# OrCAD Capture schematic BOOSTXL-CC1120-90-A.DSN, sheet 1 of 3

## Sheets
1 CC2511: size B; title: BOOSTXL-CC1120-90; rev: A
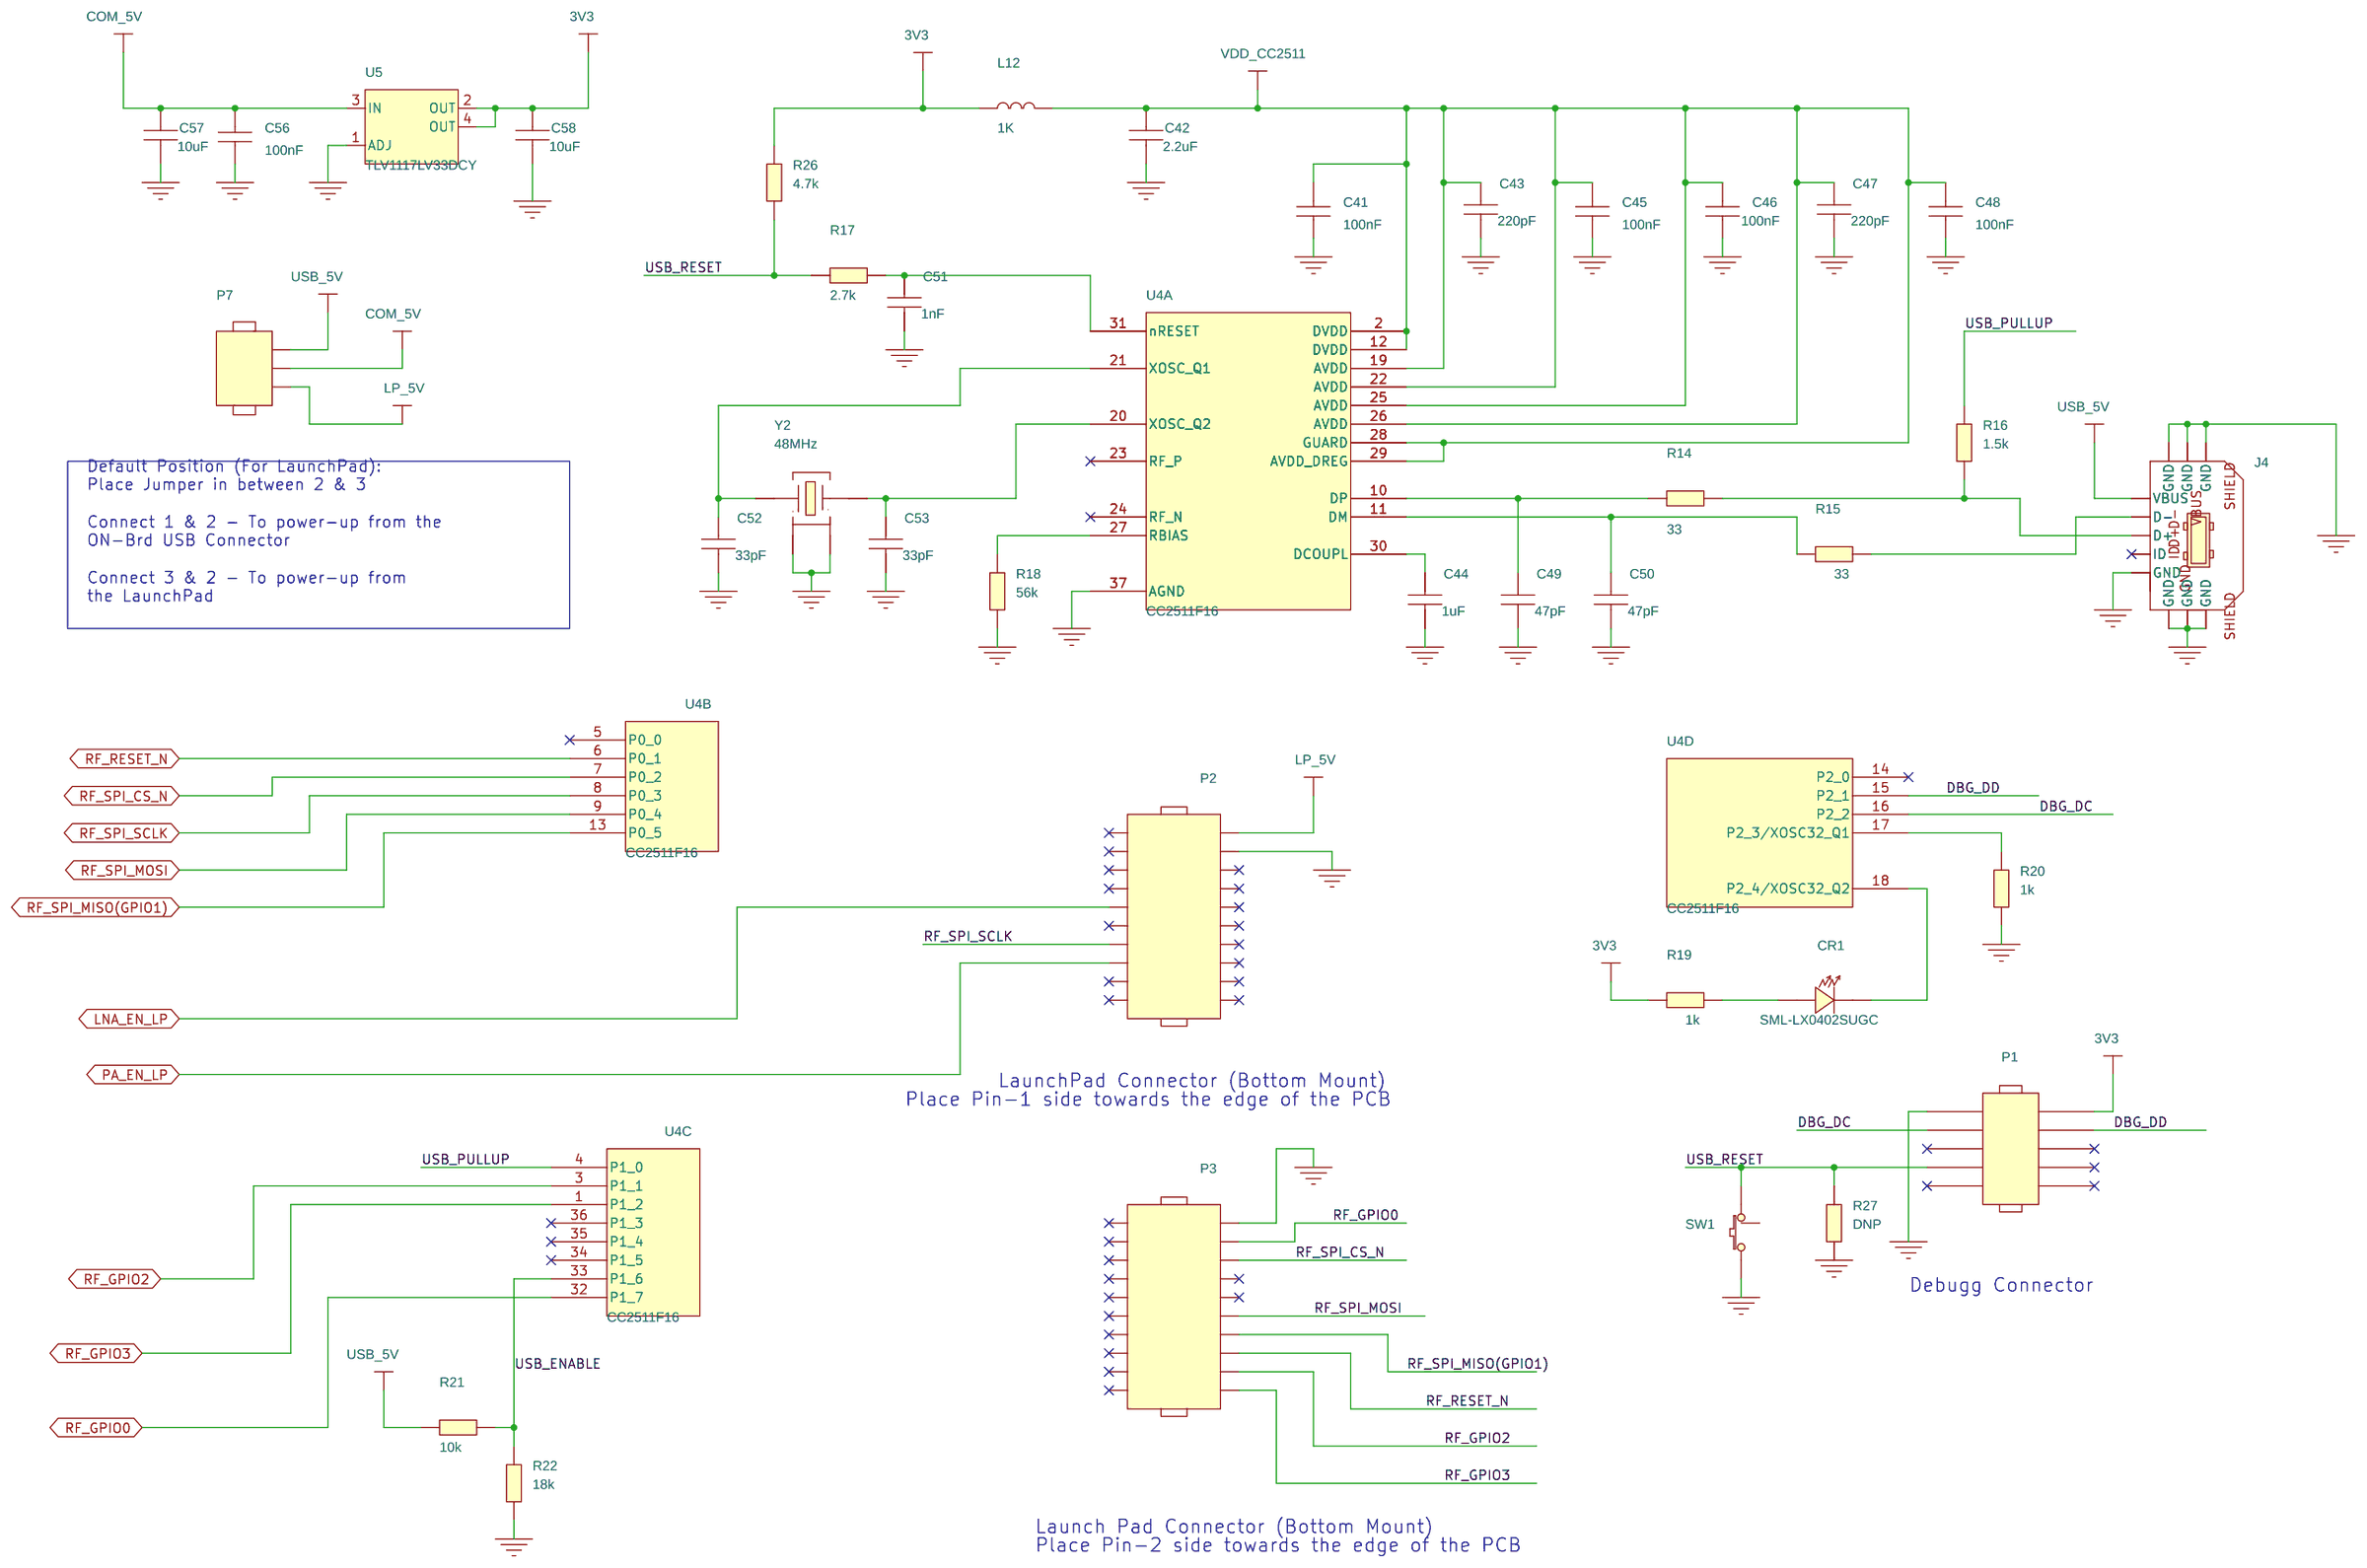
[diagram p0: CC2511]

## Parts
C41  100nF  [CAPC1005X60N]
C42  2.2uF  [CAPC1608X90N]
C43  220pF  [CAPC1005X60N]
C44  1uF  [CAPC1005X60N]
C45  100nF  [CAPC1005X60N]
C46  100nF  [CAPC1005X60N]
C47  220pF  [CAPC1005X60N]
C48  100nF  [CAPC1005X60N]
C49  47pF  [CAPC1005X60N]
C50  47pF  [CAPC1005X60N]
C51  1nF  [CAPC1005X60N]
C52  33pF  [CAPC1005X60N]
C53  33pF  [CAPC1005X60N]
C56  100nF  [CAPC1005X60N]
C57  10uF  [CAPC1608X100N]
C58  10uF  [CAPC1608X100N]
CR1  SML-LX0402SUGC  [LEDC1005X70N]
J4  1981568-1  [TYCO_19815681N]
L12  1K  [INDC1005X60N]
P1  FTSH-105-01-L-DV-K  [SAMTEC_FTSH-105-01-L-DV-K-10CN]
P2  SSW-110-23-F-D  [SAMTEC_TSW11008SDB]
P3  SSW-110-23-F-D  [SAMTEC_TSW11008SDB]
P7  TSM-103-01-L-SV-P  [SAMTEC_TSM10301LSVPN]
R14  33  [RESC1005X40N]
R15  33  [RESC1005X40N]
R16  1.5k  [RESC1005X40N]
R17  2.7k  [RESC1005X40N]
R18  56k  [RESC1005X40N]
R19  1k  [RESC1005X40N]
R20  1k  [RESC1005X40N]
R21  10k  [RESC1005X40N]
R22  18k  [RESC1005X40N]
R26  4.7k  [RESC1005X40N]
R27  DNP  [RESC1005X40N]
SW1  B3U-1000PM  [SW_B3U-1000PN]
U4  CC2511F16  [QFNWB50P600X600X90-37N]  (sections A,B,C,D)
U5  TLV1117LV33DCY  [SOT230P700X180-4AN]
Y2  48MHz  [XTAL_FA128N]

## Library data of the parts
C41 C45 C46 C48 C56 = CAPACITOR: CAPACITOR, CERAMIC X7R, 100nF, 10V, -10%/+10%, -55DEGC/+125DEGC, 0402, SMD; ALT_SYMBOLS: CAPC1005X60L,CAPC1005X60M; AutoDoc File: http://notefied-dynamic-precision.com/DB/Apps/Desktop/Item/Object.aspx?id=49911; Budget Currency: EUR; Budget Price: 0.006; Datasheet URL 1: http://search.murata.co.jp/Ceramy/image/img/w_hinm/L0005E.pdf; Datasheet URL 2: http://psearch.murata.com/capacitor/product/GRM155R71A104KA01%23.pdf; Definied Quality: INDUSTRIAL; Dielectric Type: X7R; Esd Level: N/A; FPLIST: CAPC1005X60N,CAPC1005X60L,CAPC1005X60M; Last Time Buy: N/A; Lead Time: 14; LifeCycle Status: GROWTH; MPN: GRM155R71A104KA01D; MPN Status: NRND; MSL: 1; MTBF: N/A; MTBF Standard: N/A; Manufacturer: MURATA; Max Oper Temp: +125DEGC; Max Tol: +10%; Min Oper Temp: -55DEGC; Min Tol: -10%; Mounting Type: SMD; NOTE Status: PREFERRED; Old Footprint: CAPC1005X60N,0402; PCB Package: 0402; Packing Size: 10000; Packing Type: TAPE_&_REEL; Part Number: 02-00760; Part Type: CAPACITOR\CERAMIC\0402; Revision: R008; RoHS Status: ROHS_COMPLIANT; Rtd Voltage: 10V; WEIGHT: 0.0016g
C42 = CAPACITOR: CAPACITOR, CERAMIC X5R, 2.2uF, 10V, -20%/+20%, -55DEGC/+85DEGC, 0603, SMD; ALT_SYMBOLS: CAPC1608X90L,CAPC1608X90M; AutoDoc File: http://notefied-dynamic-precision.com/DB/Apps/Desktop/Item/Object.aspx?id=50283; Budget Currency: EUR; Budget Price: 0.03; Datasheet URL 1: http://search.murata.co.jp/Ceramy/image/img/w_hinm/L0005E.pdf; Datasheet URL 2: http://psearch.murata.com/capacitor/product/GRM188R61A225ME34%23.pdf; Definied Quality: INDUSTRIAL; Dielectric Type: X5R; Esd Level: N/A; FPLIST: CAPC1608X90N,CAPC1608X90L,CAPC1608X90M; Last Time Buy: N/A; Lead Time: 10; LifeCycle Status: GROWTH; MPN: GRM188R61A225ME34D; MPN Status: NRND; MSL: 1; MTBF: N/A; MTBF Standard: N/A; Manufacturer: MURATA; Max Oper Temp: +85DEGC; Max Tol: +20%; Min Oper Temp: -55DEGC; Min Tol: -20%; Mounting Type: SMD; NOTE Status: PREFERRED; Old Footprint: CAPC1608X90N,0603; PCB Package: 0603; Packing Size: 4000; Packing Type: TAPE_&_REEL; Part Number: 02-01132; Part Type: CAPACITOR\CERAMIC\0603; Revision: R002; RoHS Status: ROHS_COMPLIANT; Rtd Voltage: 10V; WEIGHT: 0.0063g
C43 C47 = CAPACITOR: CAPACITOR, CERAMIC C0G/NP0, 220pF, 50V, -5%/+5%, -55DEGC/+125DEGC, 0402, SMD; ALT_SYMBOLS: CAPC1005X60L,CAPC1005X60M; AutoDoc File: http://notefied-dynamic-precision.com/DB/Apps/Desktop/Item/Object.aspx?id=50427; Budget Currency: EUR; Budget Price: 0.006; Datasheet URL 1: http://search.murata.co.jp/Ceramy/image/img/w_hinm/L0005E.pdf; Datasheet URL 2: http://psearch.murata.com/capacitor/product/GRM1555C1H221JA01%23.pdf; Definied Quality: INDUSTRIAL; Dielectric Type: C0G/NP0; Esd Level: N/A; FPLIST: CAPC1005X60N,CAPC1005X60L,CAPC1005X60M; Last Time Buy: N/A; Lead Time: 12; LifeCycle Status: GROWTH; MPN: GRM1555C1H221JA01D; MPN Status: ACTIVE; MSL: 1; MTBF: N/A; MTBF Standard: N/A; Manufacturer: MURATA; Max Oper Temp: +125DEGC; Max Tol: +5%; Min Oper Temp: -55DEGC; Min Tol: -5%; Mounting Type: SMD; NOTE Status: PREFERRED; Old Footprint: CAPC1005X60N,0402; PCB Package: 0402; Packing Size: 10000; Packing Type: TAPE_&_REEL; Part Number: 02-01276; Part Type: CAPACITOR\CERAMIC\0402; Revision: R001; RoHS Status: ROHS_COMPLIANT; Rtd Voltage: 50V; WEIGHT: 0.0016g
C44 = CAPACITOR: CAPACITOR, CERAMIC X5R, 1uF, 10V, -10%/+10%, -55DEGC/+85DEGC, 0402, SMD; ALT_SYMBOLS: CAPC1005X60L,CAPC1005X60M; AutoDoc File: http://notefied-dynamic-precision.com/DB/Apps/Desktop/Item/Object.aspx?id=74236; Budget Currency: EUR; Budget Price: 0.015; Datasheet URL 1: http://search.murata.co.jp/Ceramy/image/img/w_hinm/L0005E.pdf; Datasheet URL 2: http://psearch.murata.com/capacitor/product/GRM155R61A105KE15%23.pdf; Definied Quality: INDUSTRIAL; Dielectric Type: X5R; Esd Level: N/A; FPLIST: CAPC1005X60N,CAPC1005X60L,CAPC1005X60M; Last Time Buy: N/A; Lead Time: 14; MPN: GRM155R61A105KE15D; MPN Status: NRND; MSL: 1; MTBF: N/A; MTBF Standard: N/A; Manufacturer: MURATA; Max Oper Temp: +85DEGC; Max Tol: +10%; Min Oper Temp: -55DEGC; Min Tol: -10%; Mounting Type: SMD; NOTE Status: PREFERRED; Old Footprint: CAPC1005X60N,0402; PCB Package: 0402; Packing Size: 10000; Packing Type: TAPE_&_REEL; Part Number: 02-02381; Part Type: CAPACITOR\CERAMIC\0402; Revision: R005; RoHS Status: ROHS_COMPLIANT; Rtd Voltage: 10V; WEIGHT: 0.0016g
C49 C50 = CAPACITOR: CAPACITOR, CERAMIC C0G/NP0, 47pF, 50V, -5%/+5%, -55DEGC/+125DEGC, 0402, SMD; ALT_SYMBOLS: CAPC1005X60L,CAPC1005X60M; AutoDoc File: http://notefied-dynamic-precision.com/DB/Apps/Desktop/Item/Object.aspx?id=86073; Budget Currency: EUR; Budget Price: 0.006; Datasheet URL 1: http://search.murata.co.jp/Ceramy/image/img/w_hinm/L0005E.pdf; Datasheet URL 2: http://psearch.murata.com/capacitor/product/GRM1555C1H470JA01%23.pdf; Definied Quality: INDUSTRIAL; Dielectric Type: C0G/NP0; Esd Level: N/A; FPLIST: CAPC1005X60N,CAPC1005X60L,CAPC1005X60M; Last Time Buy: N/A; Lead Time: 12; MPN: GRM1555C1H470JA01D; MPN Status: ACTIVE; MSL: 1; MTBF: N/A; MTBF Standard: N/A; Manufacturer: MURATA; Max Oper Temp: +125DEGC; Max TC: +30PPM/DEGC; Max Tol: +5%; Min Oper Temp: -55DEGC; Min TC: -30PPM/DEGC; Min Tol: -5%; Mounting Type: SMD; NOTE Status: PREFERRED; PCB Package: 0402; Packing Size: 10000; Packing Type: TAPE_&_REEL; Part Number: 02-04366; Part Type: CAPACITOR\CERAMIC\0402; Revision: R001; RoHS Status: ROHS_COMPLIANT; Rtd Voltage: 50V; WEIGHT: 0.0016g
C51 = CAPACITOR: CAPACITOR, CERAMIC X7R, 1nF, 50V, -10%/+10%, -55DEGC/+125DEGC, 0402, SMD; ALT_SYMBOLS: CAPC1005X60L,CAPC1005X60M; AutoDoc File: http://notefied-dynamic-precision.com/DB/Apps/Desktop/Item/Object.aspx?id=72148; Budget Currency: EUR; Budget Price: 0.003; Datasheet URL 1: http://search.murata.co.jp/Ceramy/image/img/w_hinm/L0005E.pdf; Datasheet URL 2: http://psearch.murata.com/capacitor/product/GRM155R71H102KA01%23.pdf; Definied Quality: INDUSTRIAL; Dielectric Type: X7R; Esd Level: N/A; FPLIST: CAPC1005X60N,CAPC1005X60L,CAPC1005X60M; Last Time Buy: N/A; Lead Time: 10; LifeCycle Status: GROWTH; MPN: GRM155R71H102KA01D; MPN Status: ACTIVE; MSL: 1; MTBF: N/A; MTBF Standard: N/A; Manufacturer: MURATA; Max Oper Temp: +125DEGC; Max Tol: +10%; Min Oper Temp: -55DEGC; Min Tol: -10%; Mounting Type: SMD; NOTE Status: PREFERRED; Old Footprint: CAPC1005X60N,0402; PCB Package: 0402; Packing Size: 10000; Packing Type: TAPE_&_REEL; Part Number: 02-02070; Part Type: CAPACITOR\CERAMIC\0402; Revision: R000; RoHS Status: ROHS_COMPLIANT; Rtd Voltage: 50V; WEIGHT: 0.0016g
C52 C53 = CAPACITOR: CAPACITOR, CERAMIC C0G/NP0, 33pF, 50V, -5%/+5%, -55DEGC/+125DEGC, 0402, SMD; ALT_SYMBOLS: CAPC1005X60M,CAPC1005X60L; AutoDoc File: http://notefied-dynamic-precision.com/DB/Apps/Desktop/Item/Object.aspx?id=86036; Budget Currency: EUR; Budget Price: 0.006; Datasheet URL 1: http://search.murata.co.jp/Ceramy/image/img/w_hinm/L0005E.pdf; Datasheet URL 2: http://psearch.murata.com/capacitor/product/GRM1555C1H330JA01%23.pdf; Definied Quality: INDUSTRIAL; Dielectric Type: C0G/NP0; Esd Level: N/A; FPLIST: CAPC1005X60N,CAPC1005X60M,CAPC1005X60L; Last Time Buy: N/A; Lead Time: 12; MPN: GRM1555C1H330JA01D; MPN Status: ACTIVE; MSL: 1; MTBF: N/A; MTBF Standard: N/A; Manufacturer: MURATA; Max Oper Temp: +125DEGC; Max TC: +30PPM/DEGC; Max Tol: +5%; Min Oper Temp: -55DEGC; Min TC: -30PPM/DEGC; Min Tol: -5%; Mounting Type: SMD; NOTE Status: PREFERRED; PCB Package: 0402; Packing Size: 10000; Packing Type: TAPE_&_REEL; Part Number: 02-04354; Part Type: CAPACITOR\CERAMIC\0402; Revision: R003; RoHS Status: ROHS_COMPLIANT; Rtd Voltage: 50V; WEIGHT: 0.0016g
C57 C58 = CAPACITOR: CAPACITOR, CERAMIC X5R, 10uF, 16V, -20%/+20%, -55DEGC/+85DEGC, 0603, SMD; ALT_SYMBOLS: CAPC1608X100L,CAPC1608X100M; AutoDoc File: http://notefied-dynamic-precision.com/DB/Apps/Desktop/Item/Object.aspx?id=94995; Budget Currency: EUR; Budget Price: 0.12; Datasheet URL 1: N/A; Datasheet URL 2: http://www.yuden.co.jp/eu/product/category/capacitor/EMK107BBJ106MA-T.pdf; Definied Quality: INDUSTRIAL; Dielectric Type: X5R; Esd Level: N/A; FPLIST: CAPC1608X100N,CAPC1608X100L,CAPC1608X100M; Last Time Buy: N/A; Lead Time: 5; MPN: EMK107BBJ106MA-T; MPN Status: ACTIVE; MSL: N/A; MTBF: N/A; MTBF Standard: N/A; Manufacturer: TAIYO YUDEN; Max Oper Temp: +85DEGC; Max Tol: +20%; Min Oper Temp: -55DEGC; Min Tol: -20%; Mounting Type: SMD; NOTE Status: PREFERRED; PCB Package: 0603; Packing Size: 4000; Packing Type: TAPE_&_REEL; Part Number: 02-05939; Part Type: CAPACITOR\CERAMIC\0603; Revision: R001; RoHS Status: ROHS_COMPLIANT; Rtd Voltage: 16V; WEIGHT: N/A
CR1 = LED_AC_0: OPTO, LED, GREEN COLOR, 574nm, 0.025A, 0.1W, 0402, SMD; ALT_SYMBOLS: LEDC1005X70L,LEDC1005X70M; AutoDoc File: http://notefied-dynamic-precision.com/DB/Apps/Desktop/Item/Object.aspx?id=80253; Budget Currency: EUR; Budget Price: 0.325; Datasheet URL 1: http://www.lumex.com/images/Lumex_RoHS_Declaration_2008.doc.pdf; Datasheet URL 2: http://www.lumex.com/specs/SML-LX0402SUGC-TR.pdf; Definied Quality: INDUSTRIAL; Esd Level: N/A; FPLIST: LEDC1005X70N,LEDC1005X70L,LEDC1005X70M; Last Time Buy: N/A; Lead Time: 12; MPN: SML-LX0402SUGC-TR; MPN Status: ACTIVE; MSL: 3; MTBF: 3.55*10^7; MTBF Standard: CL=60%,Ta=100degC,Ea=0.7eV,Ts=40degC; Manufacturer: LUMEX; Max Oper Temp: +85DEGC; Min Oper Temp: -40DEGC; Mounting Type: SMD; NOTE Status: PREFERRED; PCB Package: 0402; Packing Size: 2000; Packing Type: TAPE_&_REEL; Part Number: 15-00978; Part Type: OPTO\LED\0402; Revision: R001; RoHS Status: ROHS_COMPLIANT; Rtd Current: 0.025A; Rtd Power: 0.1W; Rtd Voltage: 2.2V; WEIGHT: 0.002554g
J4 = CONN_USB_MICRO_5+6_S: CONNECTOR, USB, MICROUSB-B, RIGHT ANGLE, 5 PINS, PITCH 0.65mm, SMD; ALT_SYMBOLS: TYCO_19815681L,TYCO_19815681M; AutoDoc File: http://notefied-dynamic-precision.com/DB/Apps/Desktop/Item/Object.aspx?id=85543; Budget Currency: USD; Budget Price: 0.91080; Datasheet URL 1: http://www.te.com/commerce/DocumentDelivery/DDEController?Action=showdoc&DocId=Customer+Drawing%7F1981568%7FE1%7Fpdf%7FEnglish%7FENG_CD_1981568_E1.pdf%7F1981568-1; Datasheet URL 2: http://www.te.com/commerce/DocumentDelivery/DDEController?Action=showdoc&DocId=Data+Sheet%7F5-1773464-3%7F1012%7Fpdf%7FEnglish%7FENG_DS_5-1773464-3_1012.pdf%7F1981568-1; Definied Quality: COMMERCIAL; Esd Level: N/A; FPLIST: TYCO_19815681N,TYCO_19815681L,TYCO_19815681M; Last Time Buy: N/A; Lead Time: 14; MPN Status: ACTIVE; MSL: N/A; MTBF: N/A; MTBF Standard: N/A; Manufacturer: TE CONNECTIVITY; Max Oper Temp: N/A; Min Oper Temp: N/A; Mounting Type: SMD; NOTE Status: PREFERRED; No Of Pos: 5; No Of Rows: 1; Packing Size: 1000; Packing Type: TAPE_&_REEL; Part Number: 06-02244; Part Type: CONNECTOR\USB\MICRO_USB-B; Pitch: 0.65mm; Revision: R001; RoHS Status: ROHS_COMPLIANT; WEIGHT: 0.222g
L12 = INDUCTOR_12: FILTER, EMI, 1000@100MHz, -55DEGC/+125DEGC, 0402, SMD; ALT_SYMBOLS: INDC1005X60L,INDC1005X60M; AutoDoc File: http://notefied-dynamic-precision.com/DB/Apps/Desktop/Item/Object.aspx?id=15260; Budget Currency: EUR; Budget Price: 0.05; Datasheet URL 1: http://search.murata.co.jp/Ceramy/image/img/w_hinm/L0110E.pdf; Datasheet URL 2: http://search.murata.co.jp/Ceramy/image/img/PDF/ENG/L0110S0101BLM15H.pdf; Definied Quality: INDUSTRIAL; Esd Level: N/A; FPLIST: INDC1005X60N,INDC1005X60L,INDC1005X60M; Frequency: 100MHz; Impedance: 1000@100MHz; Last Time Buy: N/A; Lead Time: 8; LifeCycle Status: ACTIVE; MPN: BLM15HG102SN1D; MPN Status: ACTIVE; MSL: N/A; MTBF: N/A; MTBF Standard: N/A; Manufacturer: MURATA; Max Oper Temp: +125DEGC; Max Tol: +25%; Min Oper Temp: -55DEGC; Min Tol: -25%; Mounting Type: SMD; NOTE Status: PREFERRED; Old Footprint: INDC1005X60N,0402; PCB Package: 0402; Packing Size: 10000; Packing Type: TAPE_&_REEL; Part Number: 04-00032; Part Type: FILTER\EMI\0402; Resistance: 1.1; Revision: R002; RoHS Status: ROHS_COMPLIANT; Rtd Current: 0.25A; WEIGHT: 0.001g
P1 = CONN_HEADER_2X5: CONNECTOR, HEADER, MALE, STRAIGHT, 2 ROWS, 10 PINS, PITCH 1.27mm, SMD; ALT_SYMBOLS: SAMTEC_FTSH-105-01-L-DV-K-10CL,SAMTEC_FTSH-105-01-L-DV-K-10CM; AutoDoc File: http://notefied-dynamic-precision.com/DB/Apps/Desktop/Item/Object.aspx?id=51022; Budget Currency: USD; Budget Price: 1.860; Cage Code: 55322; Datasheet URL 1: http://www.samtec.com/documents/webfiles/cpdf/FTSH-1XX-XX-XXX-DV-XXX-XXX-MKT.pdf; Datasheet URL 2: http://www.samtec.com/documents/webfiles/pdf/FTSH_SMT.PDF; Definied Quality: INDUSTRIAL; Esd Level: N/A; FPLIST: SAMTEC_FTSH-105-01-L-DV-K-10CN,SAMTEC_FTSH-105-01-L-DV-K-10CL,SAMTEC_FTSH-105-01-L-DV-K-10CM; Last Time Buy: N/A; Lead Time: 2; MPN Status: ACTIVE; MSL: N/A; MTBF: N/A; MTBF Standard: N/A; Manufacturer: SAMTEC; Max Oper Temp: +125DEGC; Min Oper Temp: -55DEGC; Mounting Type: SMD; NOTE Status: PREFERRED; No Of Pos: 10; No Of Rows: 2; Packing Size: 92; Packing Type: TUBE; Part Number: 06-00352; Part Type: CONNECTOR\HEADER; Pitch: 1.27mm; Revision: R007; RoHS Status: ROHS_COMPLIANT; WEIGHT: 0.31861g
P2 P3 = CONN_HEADER_2X10_P_S_V1: CONNECTOR, HEADER, MALE, STRAIGHT, 2 ROWS, 20 PINS, PITCH 2.54mm, PTH; ALT_SYMBOLS: SAMTEC_TSW11008SDC,SAMTEC_TSW11008SDA; AutoDoc File: http://notefied-dynamic-precision.com/DB/Apps/Desktop/Item/Object.aspx?id=89340; Budget Currency: USD; Budget Price: 1.68; Datasheet URL 1: http://www.samtec.com/documents/webfiles/cpdf/TSW-XXX-XX-XXX-X-XX-XXX-MKT.pdf; Datasheet URL 2: http://www.samtec.com/documents/webfiles/pdf/TSW_TH.PDF; Definied Quality: INDUSTRIAL; Esd Level: N/A; FPLIST: SAMTEC_TSW11008SDB,SAMTEC_TSW11008SDC,SAMTEC_TSW11008SDA; Last Time Buy: N/A; Lead Time: N/A; MPN: TSW-110-08-S-D; MPN Status: ACTIVE; MSL: N/A; MTBF: N/A; MTBF Standard: N/A; Manufacturer: SAMTEC; Max Oper Temp: +125DEGC; Min Oper Temp: -55DEGC; Mounting Type: PTH; NOTE Status: PREFERRED; No Of Pos: 20; No Of Rows: 2; Packing Size: 1; Packing Type: BULK; Part Number: 06-03027; Part Type: CONNECTOR\HEADER; Pitch: 2.54mm; Revision: R001; RoHS Status: ROHS_COMPLIANT; Rtd Voltage: 500V; WEIGHT: 1.31803g
P7 = CONN_HEADER_3_P_S: CONNECTOR, HEADER, MALE, STRAIGHT, 1 ROW, 3 PINS, PITCH 2.54mm, SMD; ALT_SYMBOLS: SAMTEC_TSM10301LSVPL,SAMTEC_TSM10301LSVPM; AutoDoc File: http://notefied-dynamic-precision.com/DB/Apps/Desktop/Item/Object.aspx?id=96603; Budget Currency: USD; Budget Price: 0.545; Datasheet URL 1: http://www.samtec.com/documents/webfiles/cpdf/TSM-1XX-XX-XXX-SV-XX-XXX-XX-MKT.pdf; Datasheet URL 2: http://cloud.samtec.com/catalog_english/TSM.PDF; Definied Quality: INDUSTRIAL; Esd Level: N/A; FPLIST: SAMTEC_TSM10301LSVPN,SAMTEC_TSM10301LSVPL,SAMTEC_TSM10301LSVPM; Last Time Buy: N/A; Lead Time: 2; MPN: TSM-103-01-L-SV-P-TR; MPN Status: ACTIVE; MSL: N/A; MTBF: N/A; MTBF Standard: N/A; Manufacturer: SAMTEC; Max Oper Temp: +125DEGC; Min Oper Temp: -55DEGC; Mounting Type: SMD; NOTE Status: PREFERRED; No Of Pos: 3; No Of Rows: 1; Packing Size: 125; Packing Type: TAPE_&_REEL; Part Number: 06-03627; Part Type: CONNECTOR\HEADER; Pitch: 2.54mm; Revision: R001; RoHS Status: ROHS_COMPLIANT; Rtd Current: 4.1A/4.9A/5.4A; Rtd Voltage: 475V; WEIGHT: 0.29562g
R14 R15 = RESISTOR: RESISTOR, THICK FILM, 33, -5%/+5%, 0.063W, 50V, -55DEGC/+155DEGC, 0402, SMD; ALT_SYMBOLS: RESC1005X40L,RESC1005X40M; AutoDoc File: http://notefied-dynamic-precision.com/DB/Apps/Desktop/Item/Object.aspx?id=75679; Budget Currency: USD; Budget Price: 0.00244; Datasheet URL 1: N/A; Datasheet URL 2: N/A; Definied Quality: INDUSTRIAL; Esd Level: N/A; FPLIST: RESC1005X40N,RESC1005X40L,RESC1005X40M; Last Time Buy: N/A; Lead Time: N/A; LifeCycle Status: ACTIVE; MPN: RESISTOR_0402_33_+/-5%_50V_0.063W_M_+/-200ppm; MPN Status: ACTIVE; MSL: N/A; MTBF: N/A; MTBF Standard: N/A; Manufacturer: MANUFACTURER SELECTION; Max Oper Temp: +155DEGC; Max TC: +200PPM/DEGC; Max Tol: +5%; Min Oper Temp: -55DEGC; Min TC: -200PPM/DEGC; Min Tol: -5%; Mounting Type: SMD; NOTE Status: PREFERRED; PCB Package: 0402; Packing Size: 10000; Packing Type: TAPE_&_REEL; Part Number: 01-11624; Part Type: RESISTOR\0402; Resistor Type: THICK FILM; Revision: R000; RoHS Status: ROHS_COMPLIANT; Rtd Power: 0.063W; Rtd Voltage: 50V; WEIGHT: N/A
R16 = RESISTOR: RESISTOR, THICK FILM, 1.5k, -5%/+5%, 0.063W, 50V, -55DEGC/+155DEGC, 0402, SMD; ALT_SYMBOLS: RESC1005X40L,RESC1005X40M; AutoDoc File: http://notefied-dynamic-precision.com/DB/Apps/Desktop/Item/Object.aspx?id=75719; Budget Currency: USD; Budget Price: 0.00244; Datasheet URL 1: N/A; Datasheet URL 2: N/A; Definied Quality: INDUSTRIAL; Esd Level: N/A; FPLIST: RESC1005X40N,RESC1005X40L,RESC1005X40M; Last Time Buy: N/A; Lead Time: N/A; LifeCycle Status: ACTIVE; MPN: RESISTOR_0402_1.5k_+/-5%_50V_0.063W_M_+/-200ppm; MPN Status: ACTIVE; MSL: N/A; MTBF: N/A; MTBF Standard: N/A; Manufacturer: MANUFACTURER SELECTION; Max Oper Temp: +155DEGC; Max TC: +200PPM/DEGC; Max Tol: +5%; Min Oper Temp: -55DEGC; Min TC: -200PPM/DEGC; Min Tol: -5%; Mounting Type: SMD; NOTE Status: PREFERRED; PCB Package: 0402; Packing Size: 10000; Packing Type: TAPE_&_REEL; Part Number: 01-11664; Part Type: RESISTOR\0402; Resistor Type: THICK FILM; Revision: R000; RoHS Status: ROHS_COMPLIANT; Rtd Power: 0.063W; Rtd Voltage: 50V; WEIGHT: N/A
R17 = RESISTOR: RESISTOR, THICK FILM, 2.7k, -5%/+5%, 0.063W, 50V, -55DEGC/+155DEGC, 0402, SMD; ALT_SYMBOLS: RESC1005X40L,RESC1005X40M; AutoDoc File: http://notefied-dynamic-precision.com/DB/Apps/Desktop/Item/Object.aspx?id=75725; Budget Currency: USD; Budget Price: 0.00244; Datasheet URL 1: N/A; Datasheet URL 2: N/A; Definied Quality: INDUSTRIAL; Esd Level: N/A; FPLIST: RESC1005X40N,RESC1005X40L,RESC1005X40M; Last Time Buy: N/A; Lead Time: N/A; LifeCycle Status: ACTIVE; MPN: RESISTOR_0402_2.7k_+/-5%_50V_0.063W_M_+/-200ppm; MPN Status: ACTIVE; MSL: N/A; MTBF: N/A; MTBF Standard: N/A; Manufacturer: MANUFACTURER SELECTION; Max Oper Temp: +155DEGC; Max TC: +200PPM/DEGC; Max Tol: +5%; Min Oper Temp: -55DEGC; Min TC: -200PPM/DEGC; Min Tol: -5%; Mounting Type: SMD; NOTE Status: PREFERRED; PCB Package: 0402; Packing Size: 10000; Packing Type: TAPE_&_REEL; Part Number: 01-11670; Part Type: RESISTOR\0402; Resistor Type: THICK FILM; Revision: R000; RoHS Status: ROHS_COMPLIANT; Rtd Power: 0.063W; Rtd Voltage: 50V; WEIGHT: N/A
R18 = RESISTOR: RESISTOR, THICK FILM, 56k, -5%/+5%, 0.063W, 50V, -55DEGC/+155DEGC, 0402, SMD; ALT_SYMBOLS: RESC1005X40L,RESC1005X40M; AutoDoc File: http://notefied-dynamic-precision.com/DB/Apps/Desktop/Item/Object.aspx?id=75757; Budget Currency: USD; Budget Price: 0.00244; Datasheet URL 1: N/A; Datasheet URL 2: N/A; Definied Quality: INDUSTRIAL; Esd Level: N/A; FPLIST: RESC1005X40N,RESC1005X40L,RESC1005X40M; Last Time Buy: N/A; Lead Time: N/A; LifeCycle Status: ACTIVE; MPN: RESISTOR_0402_56k_+/-5%_50V_0.063W_M_+/-200ppm; MPN Status: ACTIVE; MSL: N/A; MTBF: N/A; MTBF Standard: N/A; Manufacturer: MANUFACTURER SELECTION; Max Oper Temp: +155DEGC; Max TC: +200PPM/DEGC; Max Tol: +5%; Min Oper Temp: -55DEGC; Min TC: -200PPM/DEGC; Min Tol: -5%; Mounting Type: SMD; NOTE Status: PREFERRED; PCB Package: 0402; Packing Size: 10000; Packing Type: TAPE_&_REEL; Part Number: 01-11702; Part Type: RESISTOR\0402; Resistor Type: THICK FILM; Revision: R000; RoHS Status: ROHS_COMPLIANT; Rtd Power: 0.063W; Rtd Voltage: 50V; WEIGHT: N/A
R19 R20 = RESISTOR: RESISTOR, THICK FILM, 1k, -5%/+5%, 0.063W, 50V, -55DEGC/+155DEGC, 0402, SMD; ALT_SYMBOLS: RESC1005X40L,RESC1005X40M; AutoDoc File: http://notefied-dynamic-precision.com/DB/Apps/Desktop/Item/Object.aspx?id=75715; Budget Currency: USD; Budget Price: 0.00244; Datasheet URL 1: N/A; Datasheet URL 2: N/A; Definied Quality: INDUSTRIAL; Esd Level: N/A; FPLIST: RESC1005X40N,RESC1005X40L,RESC1005X40M; Last Time Buy: N/A; Lead Time: N/A; LifeCycle Status: ACTIVE; MPN: RESISTOR_0402_1k_+/-5%_50V_0.063W_M_+/-200ppm; MPN Status: ACTIVE; MSL: N/A; MTBF: N/A; MTBF Standard: N/A; Manufacturer: MANUFACTURER SELECTION; Max Oper Temp: +155DEGC; Max TC: +200PPM/DEGC; Max Tol: +5%; Min Oper Temp: -55DEGC; Min TC: -200PPM/DEGC; Min Tol: -5%; Mounting Type: SMD; NOTE Status: PREFERRED; PCB Package: 0402; Packing Size: 10000; Packing Type: TAPE_&_REEL; Part Number: 01-11660; Part Type: RESISTOR\0402; Resistor Type: THICK FILM; Revision: R001; RoHS Status: ROHS_COMPLIANT; Rtd Power: 0.063W; Rtd Voltage: 50V; WEIGHT: N/A
R21 = RESISTOR: RESISTOR, THICK FILM, 10k, -5%/+5%, 0.063W, 50V, -55DEGC/+155DEGC, 0402, SMD; ALT_SYMBOLS: RESC1005X40L,RESC1005X40M; AutoDoc File: http://notefied-dynamic-precision.com/DB/Apps/Desktop/Item/Object.aspx?id=75739; Budget Currency: USD; Budget Price: 0.00244; Datasheet URL 1: N/A; Datasheet URL 2: N/A; Definied Quality: INDUSTRIAL; Esd Level: N/A; FPLIST: RESC1005X40N,RESC1005X40L,RESC1005X40M; Last Time Buy: N/A; Lead Time: N/A; LifeCycle Status: ACTIVE; MPN: RESISTOR_0402_10k_+/-5%_50V_0.063W_M_+/-200ppm; MPN Status: ACTIVE; MSL: N/A; MTBF: N/A; MTBF Standard: N/A; Manufacturer: MANUFACTURER SELECTION; Max Oper Temp: +155DEGC; Max TC: +200PPM/DEGC; Max Tol: +5%; Min Oper Temp: -55DEGC; Min TC: -200PPM/DEGC; Min Tol: -5%; Mounting Type: SMD; NOTE Status: PREFERRED; PCB Package: 0402; Packing Size: 10000; Packing Type: TAPE_&_REEL; Part Number: 01-11684; Part Type: RESISTOR\0402; Resistor Type: THICK FILM; Revision: R000; RoHS Status: ROHS_COMPLIANT; Rtd Power: 0.063W; Rtd Voltage: 50V; WEIGHT: N/A
R22 = RESISTOR: RESISTOR, THICK FILM, 18k, -5%/+5%, 0.063W, 50V, -55DEGC/+155DEGC, 0402, SMD; ALT_SYMBOLS: RESC1005X40L,RESC1005X40M; AutoDoc File: http://notefied-dynamic-precision.com/DB/Apps/Desktop/Item/Object.aspx?id=75745; Budget Currency: USD; Budget Price: 0.00244; Datasheet URL 1: N/A; Datasheet URL 2: N/A; Definied Quality: INDUSTRIAL; Esd Level: N/A; FPLIST: RESC1005X40N,RESC1005X40L,RESC1005X40M; Last Time Buy: N/A; Lead Time: N/A; LifeCycle Status: ACTIVE; MPN: RESISTOR_0402_18k_+/-5%_50V_0.063W_M_+/-200ppm; MPN Status: ACTIVE; MSL: N/A; MTBF: N/A; MTBF Standard: N/A; Manufacturer: MANUFACTURER SELECTION; Max Oper Temp: +155DEGC; Max TC: +200PPM/DEGC; Max Tol: +5%; Min Oper Temp: -55DEGC; Min TC: -200PPM/DEGC; Min Tol: -5%; Mounting Type: SMD; NOTE Status: PREFERRED; PCB Package: 0402; Packing Size: 10000; Packing Type: TAPE_&_REEL; Part Number: 01-11690; Part Type: RESISTOR\0402; Resistor Type: THICK FILM; Revision: R000; RoHS Status: ROHS_COMPLIANT; Rtd Power: 0.063W; Rtd Voltage: 50V; WEIGHT: N/A
R26 = RESISTOR: RESISTOR, THICK FILM, 4.7k, -5%/+5%, 0.063W, 50V, -55DEGC/+155DEGC, 0402, SMD; ALT_SYMBOLS: RESC1005X40L,RESC1005X40M; AutoDoc File: http://notefied-dynamic-precision.com/DB/Apps/Desktop/Item/Object.aspx?id=75731; Budget Currency: USD; Budget Price: 0.00244; Datasheet URL 1: N/A; Datasheet URL 2: N/A; Definied Quality: INDUSTRIAL; Esd Level: N/A; FPLIST: RESC1005X40N,RESC1005X40L,RESC1005X40M; Last Time Buy: N/A; Lead Time: N/A; LifeCycle Status: ACTIVE; MPN: RESISTOR_0402_4.7k_+/-5%_50V_0.063W_M_+/-200ppm; MPN Status: ACTIVE; MSL: N/A; MTBF: N/A; MTBF Standard: N/A; Manufacturer: MANUFACTURER SELECTION; Max Oper Temp: +155DEGC; Max TC: +200PPM/DEGC; Max Tol: +5%; Min Oper Temp: -55DEGC; Min TC: -200PPM/DEGC; Min Tol: -5%; Mounting Type: SMD; NOTE Status: PREFERRED; PCB Package: 0402; Packing Size: 10000; Packing Type: TAPE_&_REEL; Part Number: 01-11676; Part Type: RESISTOR\0402; Resistor Type: THICK FILM; Revision: R000; RoHS Status: ROHS_COMPLIANT; Rtd Power: 0.063W; Rtd Voltage: 50V; WEIGHT: N/A
R27 = RESISTOR: RESISTOR, THICK FILM, 4.7k, -5%/+5%, 0.063W, 50V, -55DEGC/+155DEGC, 0402, SMD; ALT_SYMBOLS: RESC1005X40L,RESC1005X40M; AutoDoc File: http://notefied-dynamic-precision.com/DB/Apps/Desktop/Item/Object.aspx?id=75731; Budget Currency: USD; Budget Price: 0.00244; Datasheet URL 1: N/A; Datasheet URL 2: N/A; Definied Quality: INDUSTRIAL; Esd Level: N/A; FPLIST: RESC1005X40N,RESC1005X40L,RESC1005X40M; Last Time Buy: N/A; Lead Time: N/A; LifeCycle Status: ACTIVE; MPN: RESISTOR_0402_4.7k_+/-5%_50V_0.063W_M_+/-200ppm; MPN Status: ACTIVE; MSL: N/A; MTBF: N/A; MTBF Standard: N/A; Manufacturer: MANUFACTURER SELECTION; Max Oper Temp: +155DEGC; Max TC: +200PPM/DEGC; Max Tol: +5%; Min Oper Temp: -55DEGC; Min TC: -200PPM/DEGC; Min Tol: -5%; Mounting Type: SMD; NOTE Status: PREFERRED; PCB Package: 0402; Packing Size: 10000; Packing Type: TAPE_&_REEL; Part Number: 01-11676; Part Type: RESISTOR\0402; Resistance: 4.7k; Resistor Type: THICK FILM; Revision: R000; RoHS Status: ROHS_COMPLIANT; Rtd Power: 0.063W; Rtd Voltage: 50V; WEIGHT: N/A
SW1 = SWITCH_0: SWITCH, TACT, CUSTOM, SPST-NO, 0.05A@12V, SMD; ALT_SYMBOLS: SW_B3U-1000PL,SW_B3U-1000PM; AutoDoc File: http://notefied-dynamic-precision.com/DB/Apps/Desktop/Item/Object.aspx?id=88596; Budget Currency: EUR; Budget Price: 0.542; Datasheet URL 1: N/A; Datasheet URL 2: http://www.components.omron.com/components/web/PDFLIB.nsf/0/2DD3893C7DD33E9E862572900079E9D6/$file/B3U_1110.pdf; Definied Quality: COMMERCIAL; Esd Level: N/A; FPLIST: SW_B3U-1000PN,SW_B3U-1000PL,SW_B3U-1000PM; Last Time Buy: N/A; Lead Time: 14; MPN: B3U-1000P; MPN Status: ACTIVE; MSL: N/A; MTBF: N/A; MTBF Standard: N/A; Manufacturer: OMRON; Max Oper Temp: +70DEGC; Min Oper Temp: -25DEGC; Mounting Type: SMD; NOTE Status: PREFERRED; Packing Size: 3500; Packing Type: TAPE_&_REEL; Part Number: 08-00133; Part Type: SWITCH\TACT; Revision: R001; RoHS Status: ROHS_COMPLIANT; Rtd Current: 0.05A; Rtd Voltage: 12V; WEIGHT: 0.022g
U4 = IC_RF_CC2511F_QFN36: IC, ANALOG, SoC WITH MCU, MEMORY 2.4GHz RF TRANSCEIVER AND USB CONTROLER, 3V TO 3.6V, VQFN36, SMD; ALT_SYMBOLS: QFNWB50P600X600X90-37L,QFNWB50P600X600X90-37M; AutoDoc File: http://notefied-dynamic-precision.com/DB/Apps/Desktop/Item/Object.aspx?id=74857; Budget Currency: USD; Budget Price: 2.25; Datasheet URL 1: http://www.ti.com/lit/er/swrz014c/swrz014c.pdf; Datasheet URL 2: http://www.ti.com/lit/ds/symlink/cc2511f16.pdf; Definied Quality: COMMERCIAL; Esd Level: HBM 750V; FPLIST: QFNWB50P600X600X90-37N,QFNWB50P600X600X90-37L,QFNWB50P600X600X90-37M; Last Time Buy: N/A; Lead Time: 10; LifeCycle Status: MATURITY; MPN: CC2511F16RSPR; MPN Status: ACTIVE; MSL: 3; MTBF: 3.97*10^8; MTBF Standard: MTTF,CL=60%,Tu=55,Ea=0.7,Tt=125; Manufacturer: TEXAS INSTRUMENTS; Max Oper Temp: +85DEGC; Min Oper Temp: 0DEGC; Mounting Type: SMD; NOTE Status: PREFERRED; PCB Package: VQFN36; Packing Size: 2500; Packing Type: TAPE_&_REEL; Part Number: 18-26612; Part Type: IC\ANALOG\RF\TRANSCEIVER; Revision: R000; RoHS Status: ROHS_COMPLIANT; Rtd Voltage: 3V TO 3.6V; WEIGHT: 0.1055g
U5 = IC_PM_LM317M_SOT223-4: IC, ANALOG, 3-TERMINAL ADJUSTABLE REGULATOR, 1.25V TO 37V, SOT223-4, SMD; ALT_SYMBOLS: SOT230P700X180-4AL,SOT230P700X180-4AM; AutoDoc File: http://notefied-dynamic-precision.com/DB/Apps/Desktop/Item/Object.aspx?id=87333; Budget Currency: USD; Budget Price: 0.44; Datasheet URL 1: N/A; Datasheet URL 2: http://www.ti.com/lit/ds/symlink/lm317mq.pdf; Definied Quality: INDUSTRIAL; Esd Level: N/A; FPLIST: SOT230P700X180-4AN,SOT230P700X180-4AL,SOT230P700X180-4AM; Last Time Buy: N/A; Lead Time: 8; MPN: LM317MQDCYRG4; MPN Status: ACTIVE; MSL: 2; MTBF: 9.9*10^8; MTBF Standard: MTTF,CL=60%,Tu=55,Ea=0.7,Tt=125; Manufacturer: TEXAS INSTRUMENTS; Max Oper Temp: +125DEGC; Min Oper Temp: -40DEGC; Mounting Type: SMD; NOTE Status: PREFERRED; PCB Package: SOT223-4; Packing Size: 2500; Packing Type: TAPE_&_REEL; Part Number: 18-28141; Part Type: IC\ANALOG\PM\REGULATOR; Revision: R001; RoHS Status: ROHS_COMPLIANT; Rtd Current: 0.5A; Rtd Voltage: 1.25V TO 37V; WEIGHT: 0.1254g
Y2 = XTAL_4: CRYSTAL, OSCILATOR, 32MHz, 10pF, -10PPM/+10PPM, -40DEGC/+85DEGC, SMD; ALT_SYMBOLS: XTAL_FA128L,XTAL_FA128M; AutoDoc File: http://notefied-dynamic-precision.com/DB/Apps/Desktop/Item/Object.aspx?id=85460; Budget Currency: EUR; Budget Price: 0.545; Capacitance: 10pF; Datasheet URL 1: http://www.eea.epson.com/portal/pls/portal/docs/1/1529523.PDF; Datasheet URL 2: http://www.eea.epson.com/portal/pls/portal/docs/1/1529449.PDF; Definied Quality: INDUSTRIAL; Esd Level: N/A; FPLIST: XTAL_FA128N,XTAL_FA128L,XTAL_FA128M; Frequency: 32MHz; Last Time Buy: N/A; Lead Time: 13; MPN: FA-128 32MHz 10pF 10ppm; MPN Status: ACTIVE; MSL: N/A; MTBF: N/A; MTBF Standard: N/A; Manufacturer: EPSON; Max Oper Temp: +85DEGC; Max Tol: +10PPM; Min Oper Temp: -40DEGC; Min Tol: -10PPM; Mounting Type: SMD; NOTE Status: PREFERRED; PCB Package: SMD; Packing Size: 250; Packing Type: TAPE_&_REEL; Part Number: 12-00422; Part Type: CRYSTAL\OSCILLATOR\MEMS; Revision: R001; RoHS Status: ROHS_COMPLIANT; WEIGHT: N/A

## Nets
3V3: C58.1 L12.1 P1.2 R19.2 R26.2 U5.2(OUT) U5.4(OUT) ; also on sheet 2 3
GND: C41.1 C42.2 C43.2 C44.2 C45.1 C46.1 C47.2 C48.1 C49.2 C50.2 C51.2 C52.2 C53.2 C56.1 C57.2 C58.2 J4.5(GND) J4.6(GND) J4.7(GND) J4.8(GND) J4.9(GND) J4.10(GND) J4.11(GND) P1.1 P2.4 P3.2 R18.1 R20.2 R22.1 R27.1 SW1.2 U4.37(AGND) U5.1(ADJ) Y2.2 Y2.4 ; also on sheet 2 3
VDD_CC2511: C41.2 C42.1 C43.1 C45.2 C46.2 C47.1 C48.2 L12.2 U4.2(DVDD) U4.12(DVDD) U4.19(AVDD) U4.22(AVDD) U4.25(AVDD) U4.26(AVDD) U4.28(GUARD) U4.29(AVDD_DREG)
COM_5V: C56.2 C57.1 P7.2 U5.3(IN)
DBG_DC: P1.3 U4.16(P2_2)
DBG_DD: P1.4 U4.15(P2_1)
LNA_EN_LP: P2.9 ; also on sheet 2
LP_5V: P2.2 P7.3
PA_EN_LP: P2.15 ; also on sheet 2
RF_GPIO0: P3.4 U4.32(P1_7) ; also on sheet 2 3
RF_GPIO2: P3.18 U4.3(P1_1) ; also on sheet 2 3
RF_GPIO3: P3.20 U4.1(P1_2) ; also on sheet 3
RF_RESET_N: P3.16 U4.6(P0_1) ; also on sheet 3
RF_SPI_CS_N: P3.6 U4.7(P0_2) ; also on sheet 3
RF_SPI_MISO(GPIO1): P3.14 U4.13(P0_5) ; also on sheet 3
RF_SPI_MOSI: P3.12 U4.9(P0_4) ; also on sheet 3
RF_SPI_SCLK: P2.13 U4.8(P0_3) ; also on sheet 3
USB_5V: J4.1(VBUS) P7.1 R21.2
USB_ENABLE: R21.1 R22.2 U4.33(P1_6)
USB_PULLUP: R16.2 U4.4(P1_0)
USB_RESET: P1.7 R17.2 R26.1 R27.2 SW1.1
N349314: C44.1 U4.30(DCOUPL)
N350057: C49.1 R14.2 U4.10(DP)
N350061: J4.3(D+) R14.1 R16.1
N350083: C50.1 R15.2 U4.11(DM)
N350090: J4.2(D-) R15.1
N350965: C51.1 R17.1 U4.31(nRESET)
N351165: R18.2 U4.27(RBIAS)
N351342: C52.1 U4.21(XOSC_Q1) Y2.1
N351349: C53.1 U4.20(XOSC_Q2) Y2.3
N352690: CR1.2(C) U4.18(P2_4/XOSC32_Q2)
N352702: CR1.1(A) R19.1
N352706: R20.1 U4.17(P2_3/XOSC32_Q1)

Not connected (* = marked no-connect by the designer): J4 4(ID)*; P1 5* 6* 8* 9* 10*; P2 1* 3* 5* 6* 7* 8* 10* 11* 12* 14* 16* 17* 18* 19* 20*; P3 1* 3* 5* 7* 8* 9* 10* 11* 13* 15* 17* 19*; U4 5(P0_0)* 14(P2_0)* 23(RF_P)* 24(RF_N)* 34(P1_5)* 35(P1_4)* 36(P1_3)*

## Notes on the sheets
sheet 1
- Default Position (For LaunchPad):
  Place Jumper in between 2 & 3
- Connect 1 & 2 - To power-up from the
  ON-Brd USB Connector
- Connect 3 & 2 - To power-up from
  the LaunchPad
- LaunchPad Connector (Bottom Mount)
- Place Pin-1 side towards the edge of the PCB
- Debugg Connector
- Launch Pad Connector (Bottom Mount)
- Place Pin-2 side towards the edge of the PCB
